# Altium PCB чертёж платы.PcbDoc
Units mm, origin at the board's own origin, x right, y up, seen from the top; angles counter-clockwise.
Board outline 152.4 x 101.6 mm, 2 copper layers (Top Layer, Bottom Layer); 38 components, 63 nets, 180 pads, 31 vias.
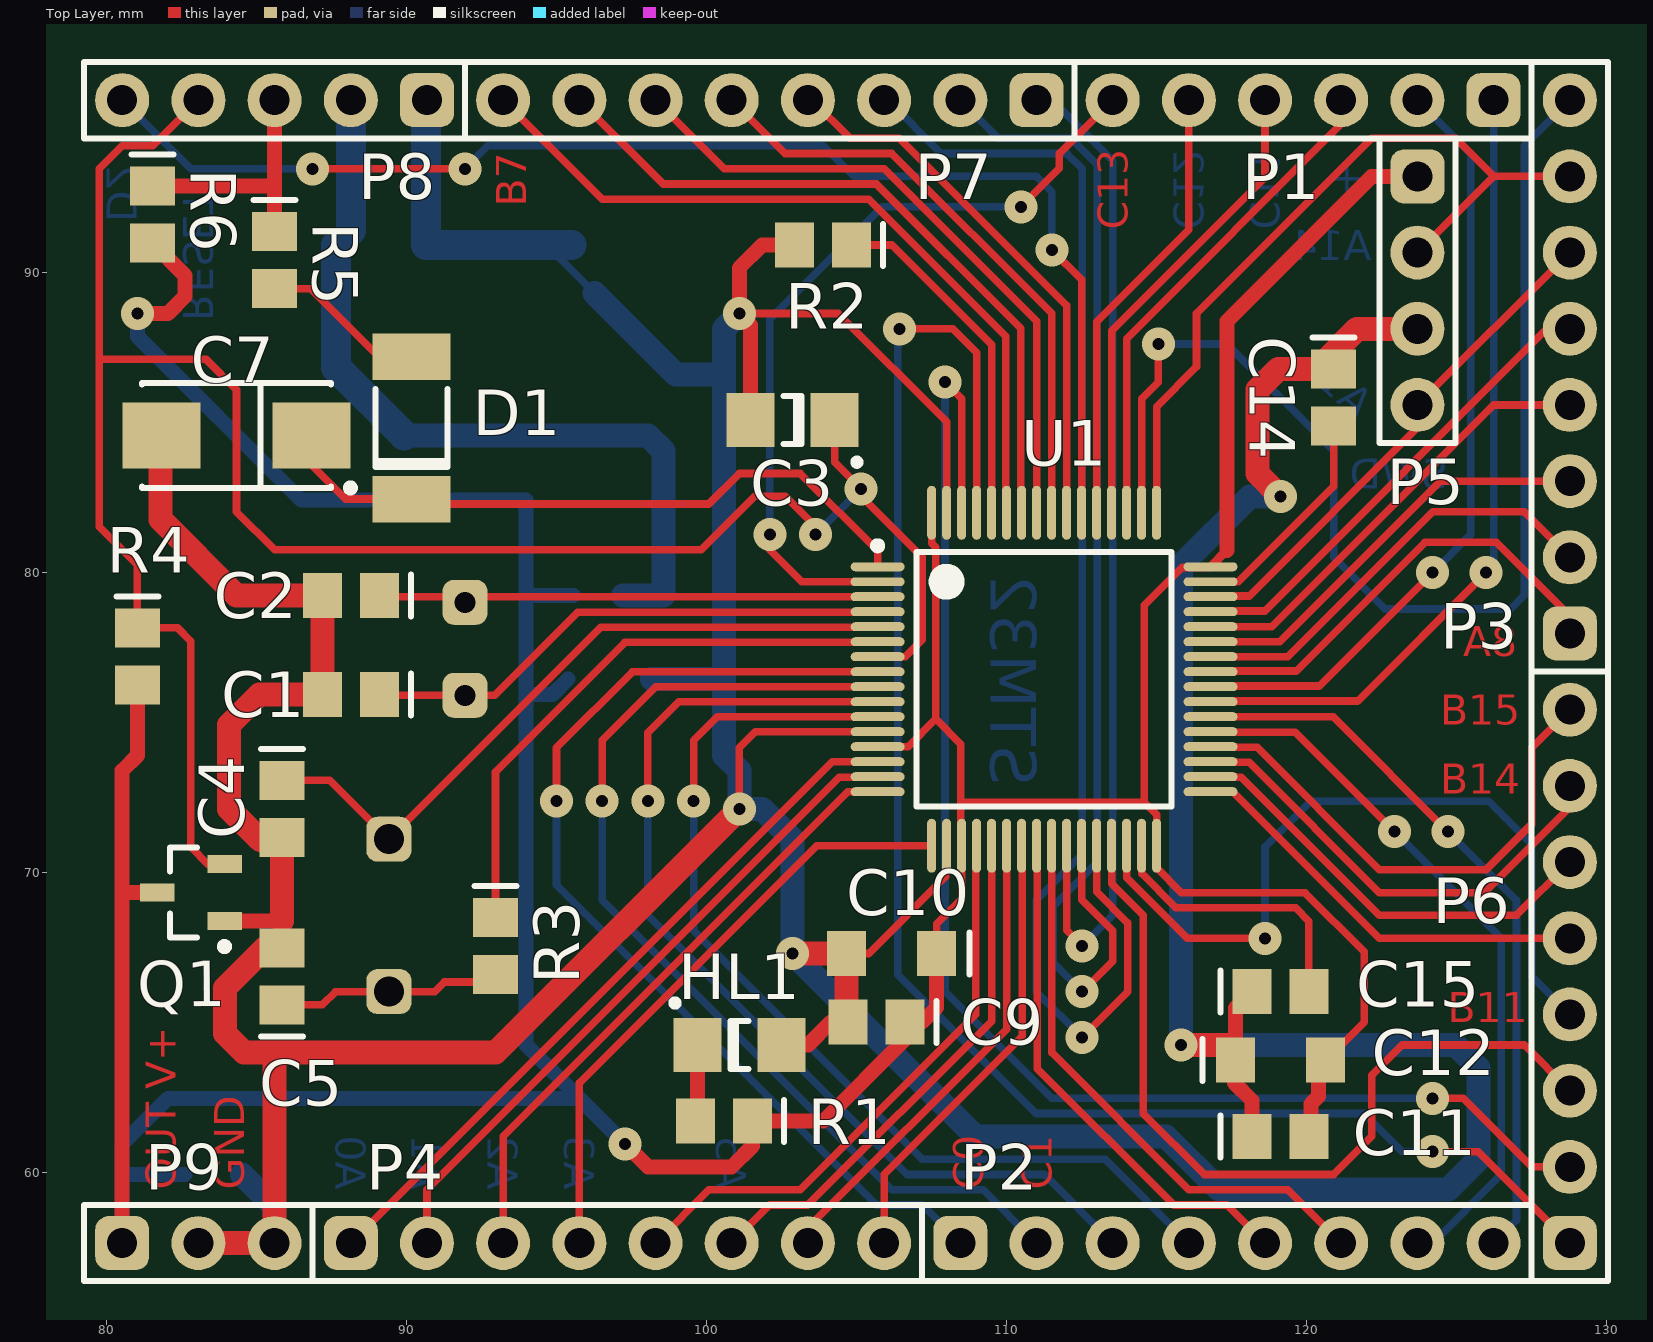
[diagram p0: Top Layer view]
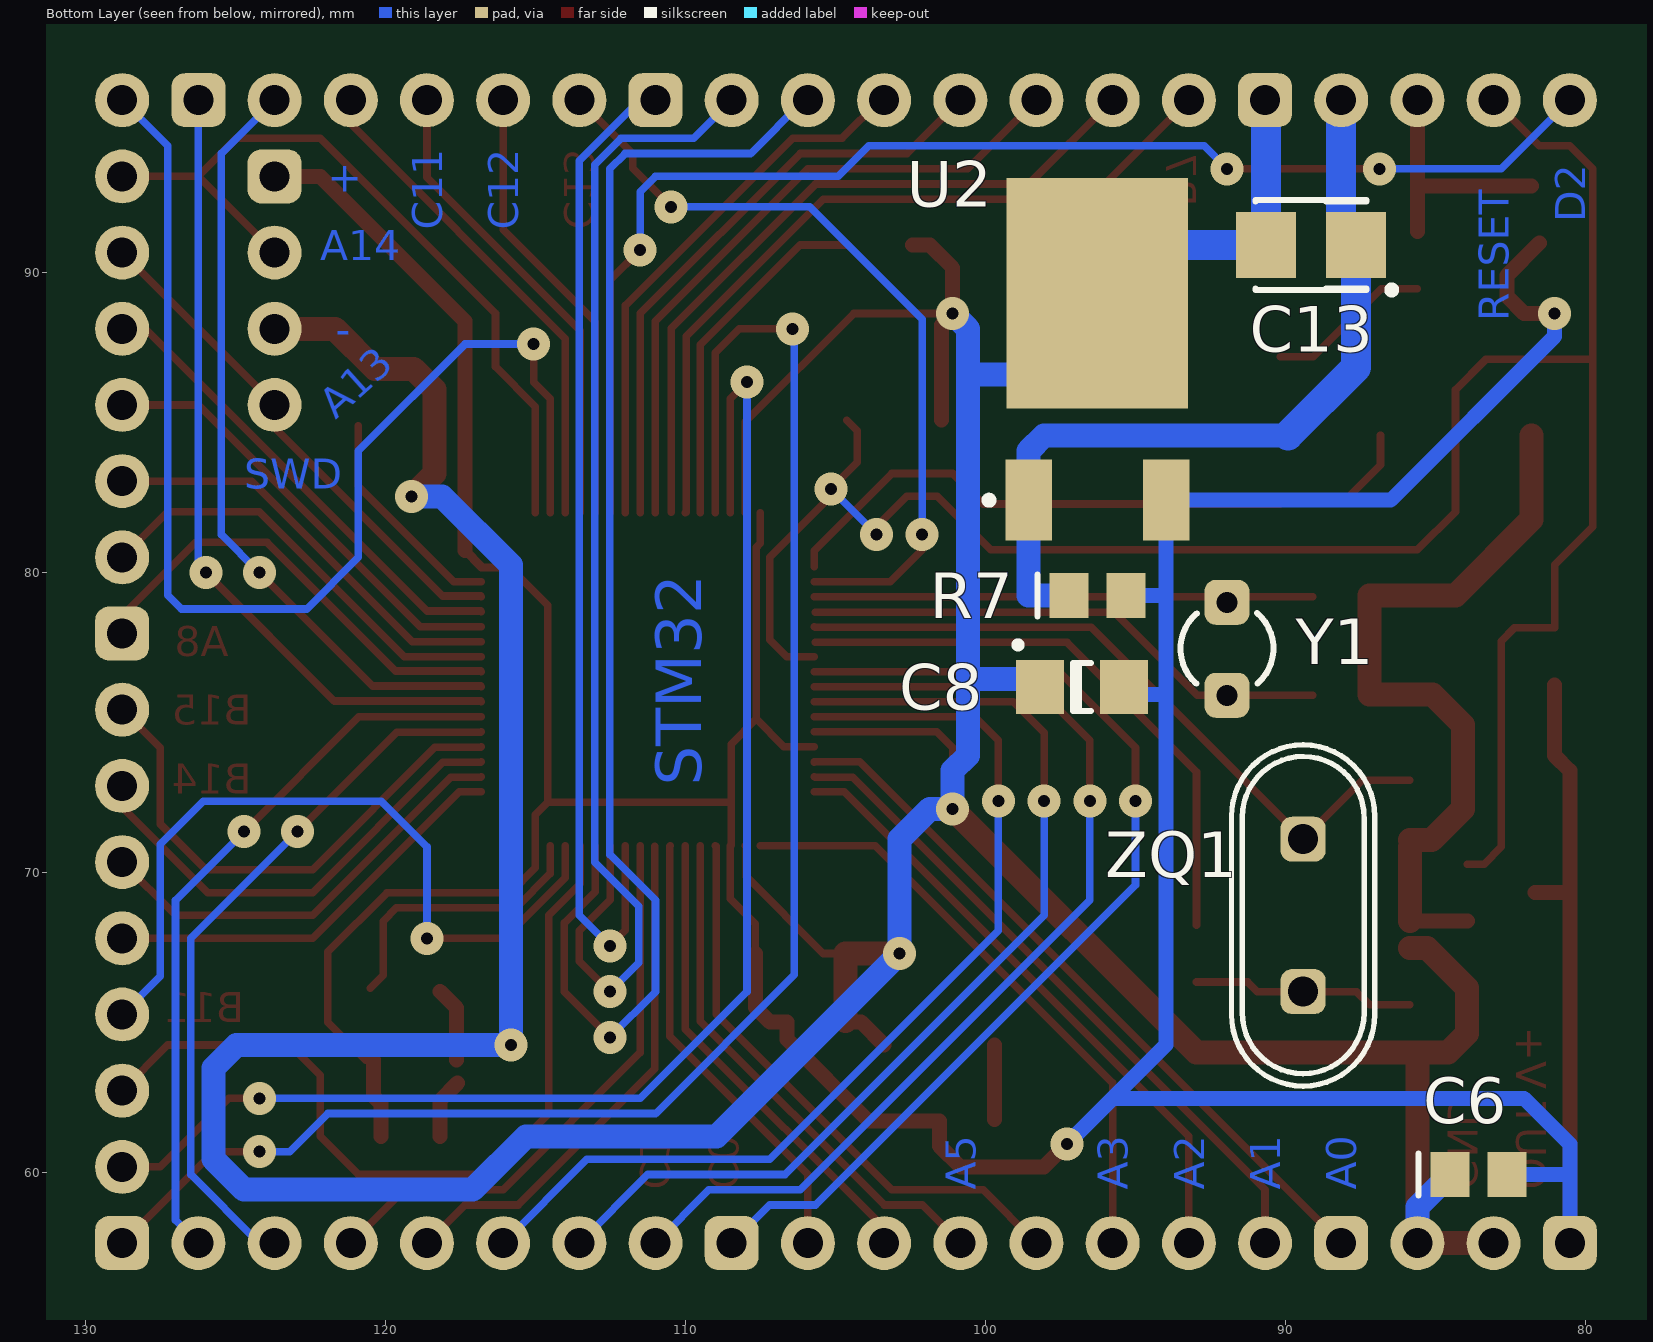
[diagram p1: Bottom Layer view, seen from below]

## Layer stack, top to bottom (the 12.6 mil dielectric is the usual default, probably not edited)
Top Solder: solder mask 0.0102, Solder Resist, Dk 3.5
Top Layer: signal copper 0.0356
Dielectric1: dielectric 0.32, FR-4, Dk 4.8
Bottom Layer: signal copper 0.0356
Bottom Solder: solder mask 0.0102, Solder Resist, Dk 3.5

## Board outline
25.4,25.4 177.8,25.4 177.8,127 25.4,127

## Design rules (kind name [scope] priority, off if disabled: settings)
Clearance [All] p1: gap=0.2
PlaneConnect [All] p1: planeconnectstyle=Relief reliefexpansion=0.254 reliefentries=4 reliefconductorwidth=0.254 reliefairgap=0.254
PolygonConnect [All] p1: connectstyle=Relief reliefconductorwidth=0.254 reliefentries=4 polygonreliefangle="45 Angle" airgapwidth=0.254
RoomDefinition Sheet1 [InComponentClass('Sheet1')] p1: confinementstyle=ConfineIn formatcopy=TRUE lockcomponents=FALSE outline 79.056,56.388 130.048,56.388 130.048,97.028 79.056,97.028
RoutingCorners [All] p1: cornerstyle=Round minsetback=2.54 maxsetback=2.54
RoutingVias [All] p1: holewidth=0.5 width=1.3 viastyle="Through Hole" minholewidth=0.5 minwidth=1 maxholewidth=0.5 maxwidth=1.5
SolderMaskExpansion [All] p1: expansion=0.2
UnpouredPolygon [All] p1: allowunpoured=FALSE
Width [All] p1: maxlimit=2 minlimit=0.254 preferedwidth=0.3
27 further rules are at their usual default settings.

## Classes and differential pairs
component class Sheet1: C1 C2 C3 C4 C5 C6 C7 C8 C9 C10 C11 C12 C13 C14 C15 D1 HL1 P1 P2 P5 P6 P7 P8 P9 Q1 R1 R3 R4 R5 R6 R7 U1 U2 Y1 ZQ1

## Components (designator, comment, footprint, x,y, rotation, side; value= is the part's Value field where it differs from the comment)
C1 "Cap Semi" C0805 88.138,75.946 r180 top
C2 "Cap Semi" C0805 88.138,79.248 r180 top
C3 "Cap Semi" C1206 102.87,85.09 r180 top
C4 "Cap Semi" C0805 85.852,72.136 r270 top
C5 "Cap Semi" C0805 85.852,66.548 r90 top
C6 "Cap Semi" C0805 83.566,59.944 r180 bottom
C7 "Cap Semi" "6032 - Type C" 84.328,84.582 r180 top
C8 "Cap Semi" C1206 96.774,76.2 r180 bottom
C9 "Cap Semi" C0805 105.664,65.024 r180 top
C10 "Cap Semi" "C0805 - wa" 106.172,67.31 r180 top
C11 "Cap Semi" C0805 119.126,61.214 r0 top
C12 "Cap Semi" "C0805 - wa" 119.126,63.754 r0 top
C13 "Cap polar_Vishay Type B" "3528 - Type B" 89.154,90.932 r0 bottom
C14 "Cap Semi" C0805 120.904,85.852 r270 top
C15 "Cap Semi" C0805 119.126,66.04 r0 top
D1 "1n4148" MELF 90.17,84.836 r270 top
HL1 "FYLS-3528UYC" C1206 101.092,64.262 r0 top
P1 "port C 8-13" HDR1X6 126.238,95.758 r180 top
P2 "port C 0-7" HDR1X8 108.458,57.658 r0 top
P3 "port A 8-15" HDR1X8 128.778,77.978 r90 top
P4 "port A 0-7" HDR1X8 88.138,57.658 r0 top
P5 "programmer" HDR1X4 123.698,93.218 r270 top
P6 "port B 8-15" HDR1X8 128.778,57.658 r90 top
P7 "port B 0-7" HDR1X8 110.998,95.758 r180 top
P8 "Header 5" HDR1X5 90.678,95.758 r180 top
P9 "Header 3" HDR1X3 80.518,57.658 r0 top
Q1 "STM809" SOT-23B_N 82.804,69.342 r180 top
R1 "Res2" C0805 100.584,61.722 r180 top
R2 "Res2" C0805 103.886,90.932 r180 top
R3 "Res2" C0805 92.964,67.564 r270 top
R4 "Resistor 1206" C0805 81.026,77.216 r270 top
R5 "Res2" C0805 85.598,90.424 r270 top
R6 "Res2" C0805 81.534,91.948 r270 top
R7 "Res2" C0805 96.266,79.248 r180 bottom
U1 "STM32F107RCT6TR" LQFP64_N 111.252,76.454 r0 top
U2 "ARU1206K-33" DPAK 96.266,87.122 r90 bottom
Y1 "32768 Hz" R38 91.948,77.47 r0 bottom
ZQ1 "8 MHz" HC49S 89.408,68.58 r90 bottom

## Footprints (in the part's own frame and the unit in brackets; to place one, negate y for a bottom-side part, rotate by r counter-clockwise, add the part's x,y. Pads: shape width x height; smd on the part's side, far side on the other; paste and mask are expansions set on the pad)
"3528 - Type B" [mm] "Capacitor, SM Tantalum; Body 3.5 x 2.8 mm (LxW typ)"
  rect 2x2.2 smd: 1(-1.5,0) 2(1.5,0)
  silkscreen extent -2.82,-1.5 1.85,1.62
"6032 - Type C" [mm] "Capacitor, SM Tantalum; Body 6.0 x 3.2 mm (LxW typ)"
  rect 2.6x2.2 smd: 1(-2.5,0) 2(2.5,0)
  silkscreen extent -3.93,-1.75 3.15,1.87
C0805 [mm] "Chip Capacitor; Body 2.0 x 1.2 mm (LxW typ)"
  rect 1.3x1.5 smd: 1(-0.95,0) 2(0.95,0)
  silkscreen extent -2,-0.7 -2,0.7
"C0805 - wa" [mm] "Chip Capacitor; Body 2.0 x 1.2 mm (LxW typ)"
  rect 1.3x1.5 smd: 1(-1.5,0) 2(1.5,0)
  silkscreen extent -2.6,-0.7 -2.6,0.7
C1206 [mm] "Chip Capacitor; Body 3.2 x 1.6 mm (LxW typ)"
  rect 1.6x1.8 smd: 1(-1.4,0) 2(1.4,0)
  silkscreen extent -2.18,-0.8 0.3,1.44
DPAK [mm] "D-PAK, 3-Pads, Body 6,2x6,6mm (max), IPC Medium Density"
  rect 2.7x1.55 smd: 1(-4.7,2.29) 3(-4.7,-2.29)
  rect 7.7x6.05 smd: 2(2.2,0)
  silkscreen extent -4.82,3.49 -4.58,3.74, body extent -5.59,-3.3 4.51,3.3, height 2.4
HC49S [mm]
  rrect50% 1.5x1.5 hole 1: 1(-2.54,0) 2(2.54,0)
  silkscreen extent -5.69,-2.39 5.69,2.39
HDR1X3 [mm] "Connector; Header; 3 Position"
  rrect50% 1.8x1.8 hole 1: 1(0,0)
  round 1.8 hole 1: 2(2.54,0) 3(5.08,0)
  silkscreen extent -1.27,-1.27 6.35,1.27
HDR1X4 [mm] "Connector; Header; 4 Position"
  rrect50% 1.8x1.8 hole 1: 1(0,0)
  round 1.8 hole 1: 2(2.54,0) 3(5.08,0) 4(7.62,0)
  silkscreen extent -1.27,-1.27 8.89,1.27
HDR1X5 [mm] "Connector; Header; 5 Position"
  rrect50% 1.8x1.8 hole 1: 1(0,0)
  round 1.8 hole 1: 2(2.54,0) 3(5.08,0) 4(7.62,0) 5(10.16,0)
  silkscreen extent -1.27,-1.27 11.43,1.27
HDR1X6 [mm] "Connector; Header; 6 Position"
  rrect50% 1.8x1.8 hole 1: 1(0,0)
  round 1.8 hole 1: 2(2.54,0) 3(5.08,0) 4(7.62,0) 5(10.16,0) 6(12.7,0)
  silkscreen extent -1.27,-1.27 13.97,1.27
HDR1X8 [mm] "Connector; Header; 8 Position"
  rrect50% 1.8x1.8 hole 1: 1(0,0)
  round 1.8 hole 1: 2(2.54,0) 3(5.08,0) 4(7.62,0) 5(10.16,0) 6(12.7,0) 7(15.24,0) 8(17.78,0)
  silkscreen extent -1.27,-1.27 19.05,1.27
LQFP64_N [mm] "Thin QFP, 64-Leads, Body 10x10mm, Pitch 0.5mm, IPC Medium Density"
  oval 1.8x0.3 smd: 1(-5.55,3.75) 2(-5.55,3.25) 3(-5.55,2.75) 4(-5.55,2.25) 5(-5.55,1.75) 6(-5.55,1.25) 7(-5.55,0.75) 8(-5.55,0.25) 9(-5.55,-0.25) 10(-5.55,-0.75) 11(-5.55,-1.25) 12(-5.55,-1.75) 13(-5.55,-2.25) 14(-5.55,-2.75) 15(-5.55,-3.25) 16(-5.55,-3.75) 33(5.55,-3.75) 34(5.55,-3.25) 35(5.55,-2.75) 36(5.55,-2.25) 37(5.55,-1.75) 38(5.55,-1.25) 39(5.55,-0.75) 40(5.55,-0.25) 41(5.55,0.25) 42(5.55,0.75) 43(5.55,1.25) 44(5.55,1.75) 45(5.55,2.25) 46(5.55,2.75) 47(5.55,3.25) 48(5.55,3.75)
  oval 0.3x1.8 smd: 17(-3.75,-5.55) 18(-3.25,-5.55) 19(-2.75,-5.55) 20(-2.25,-5.55) 21(-1.75,-5.55) 22(-1.25,-5.55) 23(-0.75,-5.55) 24(-0.25,-5.55) 25(0.25,-5.55) 26(0.75,-5.55) 27(1.25,-5.55) 28(1.75,-5.55) 29(2.25,-5.55) 30(2.75,-5.55) 31(3.25,-5.55) 32(3.75,-5.55) 49(3.75,5.55) 50(3.25,5.55) 51(2.75,5.55) 52(2.25,5.55) 53(1.75,5.55) 54(1.25,5.55) 55(0.75,5.55) 56(0.25,5.55) 57(-0.25,5.55) 58(-0.75,5.55) 59(-1.25,5.55) 60(-1.75,5.55) 61(-2.25,5.55) 62(-2.75,5.55) 63(-3.25,5.55) 64(-3.75,5.55)
  silkscreen extent -5.67,-4.25 4.25,4.57, body extent -5,-5 5,5, height 1.6
MELF [mm] "Metal Electrode Face (MELF) Diode; Body 5 x 2.5 mm (LxDia)"
  rect 1.55x2.6 smd: 1(-2.375,0) 2(2.375,0)
  silkscreen extent -1.3,-1.2 1.3,1.2
R38 [mm] "Crystal, Thru-Hole; 2 Leads; Body 3.1 x 8.2 mm (Dia.xH)"
  rrect50% 1.5x1.5 hole 0.7: 1(0,1.55) 2(0,-1.55)
  silkscreen extent -1.55,-1.19 1.55,1.17
SOT-23B_N [mm] "SOT23, 3-Leads, Body 2.9x1.3mm, Pitch 0.95mm, Lead Span 2.4mm, IPC Medium Density"
  rect 1.15x0.6 smd: 1(-1.125,0.95) 2(-1.125,-0.95) 3(1.125,0)
  silkscreen extent -1.25,-1.5 0.7,1.92, body extent -0.7,-1.5 0.7,1.5, height 1.14

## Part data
C1 C2 C3 C4 C5 C6 C7 C8 C9 C10 C11 C12 C14 C15: "Capacitor (Semiconductor SIM Model)"
C13: "Capacitor (Model Sergeev)"
D1: library part SM4001, "Диод SMD 1A, 1000V"
HL1: library part "LED CMD", "Typical INFRARED GaAs LED"
P1: library part "Header 6", "Header, 6-Pin"
P2 P3 P4 P6 P7: library part "Header 8", "Header, 8-Pin"
P5: library part "Header 4", "Header, 4-Pin"
P8: "Header, 5-Pin"
P9: "Header, 3-Pin"
Q1: library part PNP, "PNP Bipolar Transistor"
R1 R2 R3 R5 R6 R7: "Resistor"
U1: "STM32 ARM-based 32-bit MCU Connectivity Line & Ethernet with 256 kB Flash, 64 kB Internal RAM, -40 to +85°C Temperature, 64-Pin LQFP, Tape and Reel"
U2: library part L7805ABV, "Precision 1A Regulator"
Y1 ZQ1: library part XTAL, "Crystal Oscillator"

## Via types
v1: diameter 1.1, hole 0.4, Top Layer to Bottom Layer, tented both sides, 31 vias

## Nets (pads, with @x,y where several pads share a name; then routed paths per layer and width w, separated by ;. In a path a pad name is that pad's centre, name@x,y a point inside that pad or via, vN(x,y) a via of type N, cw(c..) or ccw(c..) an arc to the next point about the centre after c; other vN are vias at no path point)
GND: C1.2 C2.2 C3.2 C4.2 C5.2 C6.1 C7.2 C8.1 C9.2 C10.2 C11.1 C12.1 C13.2 C14.1 C15.1 HL1.2 P5.3 P8.1 P9.2 P9.3 Q1.1 R2.2 U1.12 U1.18 U1.63 U2.2 | length 217.1
  Top Layer w0.254: v1(101.092,72.136) 101.092,74.168 101.628,74.704 U1.12 ; v1(101.092,88.646) 104.394,88.646 108.002,85.038 U1.63 ; C10.2 105.41,67.31 107.979,69.879 107.979,70.881 U1.18
  Top Layer w0.5: Q1.1 85.852,68.392 ; C3.2 101.47,88.268 v1(101.092,88.646) 101.092,90.17 101.854,90.932 R2.2@102.428,90.932 ; 103.378,64.262 104.14,65.024 C9.2 ; 117.602,62.992 118.176,62.418 C11.1 ; C12.1 117.626,65.49 C15.1
  Top Layer w0.8: C7.2@81.803,84.582 81.803,81.773 84.328,79.248 C2.2 C1.2 85.09,75.946 84.074,74.93 84.074,72.136 85.121,71.089 C4.2@85.852,71.089 ; P9.2 P9.3 85.598,64.008 ; C5.2 85.278,67.498 83.947,66.167 83.947,64.643 84.582,64.008 85.598,64.008 ; 85.852,68.392 C4.2@85.852,70.866 ; v1(101.092,72.136) 92.964,64.008 85.598,64.008 ; v1(102.87,67.31) C10.2 C9.2@104.672,65.066 ; v1(115.824,64.262) C12.1@117.372,64.262 ; v1(119.126,82.55) 118.364,83.312 118.364,86.106 119.06,86.802 120.354,86.802 121.69,88.138 P5.3
  Bottom Layer w0.254: P8.1@90.654,95.782 P8.1 ; U2.2@94.656,90.932 U2.2
  Bottom Layer w0.8: C6.1 85.598,58.862 P9.3 ; U2.2 98.974,86.614 100.584,86.614 ; C8.1@98.174,76.454 100.584,76.454 ; v1(101.092,88.646) 100.584,88.138 100.584,86.614 ; v1(119.126,82.55) 118.11,82.55 115.824,80.264 v1(115.824,64.262) 124.968,64.262 125.73,63.5 125.73,60.452 124.714,59.436 117.094,59.436 115.316,61.214 108.966,61.214 v1(102.87,67.31) 102.87,71.12 101.854,72.136 v1(101.092,72.136) 101.092,73.406 100.584,73.914 100.584,76.454 ; 100.584,76.454 100.584,86.614
  Bottom Layer w1: P8.1@90.654,95.782 C13.2 U2.2@95.504,90.932
NetC1_1: C1.1 U1.4 Y1.1 | length 17.7
  Top Layer w0.254: C1.1@89.088,75.92 92.938,75.92 95.699,78.681 U1.4@105.679,78.681
NetC2_1: C2.1 U1.3 Y1.2 | length 16.6
  Top Layer w0.254: C2.1@89.088,79.204 U1.3
NetC3_1: C3.1 P8.4 Q1.2 R4.1 U1.7 | length 73.1
  Top Layer w0.254: 79.756,86.868 79.756,89.662 79.756,93.472 80.518,94.234 81.534,94.234 P8.4 ; Q1.2 83.378,70.292 82.804,70.866 82.804,77.724 82.362,78.166 R4.1 81.026,80.264 79.756,81.534 79.756,87.122 83.312,87.122 84.328,86.106 84.328,82.042 85.598,80.772 99.822,80.772 101.6,82.55 102.616,82.55 103.632,81.534 v1(103.632,81.28) ; C3.1@104.624,85.09 104.27,84.736 104.27,83.69 v1(105.156,82.804) ; v1@105.156,82.55 107.188,80.518 107.188,77.765 106.627,77.204 U1.7
  Bottom Layer w0.254: v1(103.632,81.28) v1(105.156,82.804)
NetC4_1: C4.1 U1.5 ZQ1.2 | length 23.6
  Top Layer w0.254: C4.1 87.442,73.086 ZQ1.2 96.469,78.181 105.679,78.181 U1.5
NetC5_1: C5.1 R3.2 ZQ1.1 | length 7.4
  Top Layer w0.254: C5.1 87.188,65.598 87.63,66.04 ZQ1.1 90.932,66.04 91.252,66.36 R3.2@92.964,66.36
NetC6_2: C6.2 C8.2 C9.1 C10.1 C11.2 C12.2 P5.1 P9.1 Q1.3 R1.1 R4.2 R6.2 R7.2 U1.13 U1.19 U1.32 U1.48 U1.64 U2.3 | length 172.1
  Top Layer w0.254: U1.13 106.716,74.204 107.642,75.13 ; U1.64 107.502,80.986 107.642,80.846 107.642,75.13 ; C10.1 107.672,68.302 108.502,69.132 U1.19 ; U1.19@108.479,70.927 108.479,72.352 ; U1.48 116.779,80.181 115.854,80.181 114.592,78.919 114.592,72.352 ; C12.2@120.65,63.754 121.92,65.024 121.92,67.37 119.948,69.342 115.824,69.342 115.002,70.164 U1.32 115.002,71.942 114.592,72.352 ; 107.642,75.13 108.479,74.293 108.479,72.352 ; 108.479,72.352 114.592,72.352
  Top Layer w0.3: U1.48 117.348,80.75
  Top Layer w0.5: P9.1 80.518,69.342 ; R4.2 81.026,73.914 80.518,73.406 80.518,69.342 ; v1(81.026,88.646) 82.042,88.646 82.616,89.22 82.616,89.916 R6.2 ; Q1.3 80.518,69.342 ; v1(97.282,60.96) 98.044,60.198 100.838,60.198 101.534,60.894 R1.1 103.886,61.722 106.614,64.45 C9.1 107.188,65.024 107.672,65.508 C10.1 ; 117.348,80.75 117.348,88.392 122.174,93.218 P5.1 ; C11.2@120.142,61.214 120.142,62.296 120.396,62.55 C12.2@120.396,63.754
  Bottom Layer w0.5: P9.1 80.518,60.96 82.042,62.484 95.758,62.484 v1(97.282,60.96) 93.976,64.266 93.976,79.252 ; 80.518,59.944 C6.2 ; v1(81.026,88.646) 81.026,87.884 86.488,82.422 U2.3 93.976,79.252 ; 93.976,75.946 94.866,75.946 C8.2@95.374,76.454 ; R7.2@95.57,79.248 93.98,79.248 93.976,79.252
NetC7_1: C7.1 D1.2 U1.1 | length 22.3
  Top Layer w0.254: C7.1 86.828,83.606 87.973,82.461 D1.2 ; D1.2@90.17,82.296 100.076,82.296 101.092,83.312 103.124,83.312 105.702,80.734 U1.1
NetC13_1: C13.1 P8.2 R7.1 U2.1 | length 27.3
  Bottom Layer w0.5: C13.1 C13.1@88.138,91.416
  Bottom Layer w0.8: 89.916,84.582 98.044,84.582 98.556,84.07 U2.1 98.556,79.252 98.552,79.248 R7.1
  Bottom Layer w1: C13.1 87.654,86.844 89.916,84.582 ; C13.1@88.138,91.416 P8.2
NetC14_2: C14.2 U1.47 | length 7.4
  Top Layer w0.254: U1.47 117.727,79.704 120.904,82.881 C14.2
NetC15_2: C15.2 U1.31 | length 9.6
  Top Layer w0.254: U1.31 114.502,69.979 115.647,68.834 119.634,68.834 120.076,68.392 120.076,66.59 C15.2@120.511,66.155
NetD1_1: D1.1 R5.2 | length 5.5
  Top Layer w0.254: R5.2 86.802,89.474 89.065,87.211 D1.1
NetHL1_1: HL1.1 R1.2 | length 2.5
  Top Layer w0.5: R1.2@99.692,61.78 HL1.1
NetP1_1: P1.1 U1.39 | length 26.9
  Top Layer w0.254: U1.39 116.825,75.727 121.701,75.727 v1(125.984,80.01)
  Bottom Layer w0.254: v1(125.984,80.01) 126.238,80.264 126.238,95.504 P1.1@125.984,95.758
NetP1_2: P1.2 U1.40 | length 26
  Top Layer w0.254: U1.40 116.825,76.227 120.423,76.227 v1(124.206,80.01)
  Bottom Layer w0.254: P1.2 125.476,93.98 125.476,81.28 v1(124.206,80.01)
NetP1_3: P1.3 U1.51 | length 16.7
  Top Layer w0.254: U1.51 114.002,87.81 121.158,94.966 P1.3
NetP1_4: P1.4 U1.52 | length 15.9
  Top Layer w0.254: U1.52 113.502,88.073 118.618,93.189 P1.4
NetP1_5: P1.5 U1.53 | length 15
  Top Layer w0.254: U1.53 113.002,88.364 116.078,91.44 P1.5
NetP1_6: P1.6 U1.2 | length 26.5
  Top Layer w0.254: v1(102.108,81.28) 102.108,80.772 103.176,79.704 U1.2 ; v1(110.474,92.202) 111.76,93.488 111.76,93.98 P1.6
  Bottom Layer w0.254: v1(102.108,81.28) 102.108,88.458 105.852,92.202 v1(110.474,92.202)
NetP2_1: P2.1 U1.8 | length 35
  Top Layer w0.254: v1@94.996,72.136 94.996,74.168 97.532,76.704 U1.8
  Bottom Layer w0.254: v1(94.996,72.39) 94.996,69.596 105.664,58.928 107.188,58.928 P2.1
NetP2_2: P2.2 U1.9 | length 34.7
  Top Layer w0.254: v1@96.52,72.136 96.52,74.422 98.302,76.204 U1.9
  Bottom Layer w0.254: v1(96.52,72.39) 96.52,69.088 106.172,59.436 109.22,59.436 P2.2
NetP2_3: P2.3 U1.10 | length 34.5
  Top Layer w0.254: v1@98.044,72.136 98.044,74.676 99.072,75.704 U1.10
  Bottom Layer w0.254: v1(98.044,72.39) 98.044,68.58 106.68,59.944 111.252,59.944 P2.3
NetP2_4: P2.4 U1.11 | length 33.6
  Top Layer w0.254: v1(99.568,72.39) 99.568,74.422 100.35,75.204 U1.11
  Bottom Layer w0.254: v1(99.568,72.39) 99.568,68.072 107.188,60.452 113.284,60.452 P2.4
NetP2_5: P2.5 U1.24 | length 17.4
  Top Layer w0.254: U1.24@111.025,70.881 111.025,63.473 115.57,58.928 117.348,58.928 P2.5
NetP2_6: P2.6 U1.25 | length 19.2
  Top Layer w0.254: U1.25 111.502,64.012 116.078,59.436 119.38,59.436 P2.6
NetP2_7: P2.7 U1.37 | length 24.2
  Top Layer w0.254: U1.37 116.825,74.681 119.629,74.681 v1(122.936,71.374)
  Bottom Layer w0.254: v1(122.936,71.374) 126.492,67.818 126.492,59.944 124.206,57.658 P2.7
NetP2_8: P2.8 U1.38 | length 24.5
  Top Layer w0.254: U1.38 120.884,75.204 v1(124.714,71.374)
  Bottom Layer w0.254: v1(124.714,71.374) 127,69.088 127,58.42 P2.8
NetP3_1: P3.1 U1.41 | length 15.4
  Top Layer w0.254: U1.41 116.825,76.727 119.653,76.727 123.952,81.026 126.328,81.026 128.778,78.576 P3.1
NetP3_2: P3.2 U1.42 | length 14.6
  Top Layer w0.254: U1.42 119.368,77.204 124.206,82.042 127.254,82.042 P3.2
NetP3_3: P3.3 U1.43 | length 14.2
  Top Layer w0.254: U1.43 119.106,77.704 124.46,83.058 P3.3
NetP3_4: P3.4 U1.44 | length 15
  Top Layer w0.254: U1.44 118.844,78.204 126.238,85.598 P3.4
NetP3_5: P3.5 U1.45 | length 15.9
  Top Layer w0.254: U1.45 116.825,78.727 118.605,78.727 128.016,88.138 P3.5
NetP3_6: P3.6 P5.4 U1.46 | length 17.2
  Top Layer w0.254: U1.46 116.825,79.227 118.089,79.227 123.698,84.836 P5.4 P3.6
NetP3_7: P3.7 P5.2 U1.49 | length 26.2
  Top Layer w0.254: U1.49 115.002,85.538 116.332,86.868 116.332,88.646 122.174,94.488 124.968,94.488 126.238,93.218 ; P5.2 126.238,93.218 ; P3.7 126.238,93.218
NetP3_8: P3.8 U1.50 | length 41.1
  Top Layer w0.254: U1.50 114.502,85.8 115.062,86.36 v1(115.062,87.63)
  Bottom Layer w0.254: v1(115.062,87.63) 117.348,87.63 120.904,84.074 120.904,80.518 122.628,78.794 126.8,78.794 127.254,79.248 127.254,94.234 P3.8
NetP4_1: P4.1 U1.14 | length 24.2
  Top Layer w0.254: P4.1 104.184,73.704 U1.14 U1.14@105.702,73.681
NetP4_2: P4.2 U1.15 | length 22.5
  Top Layer w0.254: P4.2 90.678,59.436 104.423,73.181 105.679,73.181 U1.15
NetP4_3: P4.3 U1.16 | length 20.8
  Top Layer w0.254: P4.3 93.218,61.214 104.708,72.704 U1.16
NetP4_4: P4.4 U1.17 | length 20.4
  Top Layer w0.254: P4.4 95.758,62.992 103.67,70.904 U1.17
NetP4_5: P4.5 U1.20 | length 19.5
  Top Layer w0.254: P4.5 100.076,59.436 103.124,59.436 108.979,65.291 108.979,70.881 U1.20
NetP4_6: P4.6 U1.21 | length 17.6
  Top Layer w0.254: P4.6 102.108,58.928 103.378,58.928 109.502,65.052 U1.21
NetP4_7: P4.7 U1.22 | length 16
  Top Layer w0.254: P4.7 103.378,58.166 110.002,64.79 U1.22
NetP4_8: P4.8 U1.23 | length 15.2
  Top Layer w0.254: P4.8 105.918,59.944 110.525,64.551 110.525,70.881 U1.23
NetP6_1: P6.1 U1.61 | length 55.9
  Top Layer w0.254: v1(106.426,88.138) 108.204,88.138 109.002,87.34 U1.61 ; v1(124.206,60.706) 125.73,60.706 P6.1
  Bottom Layer w0.254: v1@106.372,88.138 106.372,66.602 110.998,61.976 121.92,61.976 123.19,60.706 v1(124.206,60.706)
NetP6_2: P6.2 U1.62 | length 48.2
  Top Layer w0.254: v1(107.95,86.36) 108.502,85.808 U1.62 ; v1(124.206,62.484) 125.222,62.484 127.508,60.198 P6.2
  Bottom Layer w0.254: v1(107.95,86.36) 107.95,66.04 111.506,62.484 v1(124.206,62.484)
NetP6_3: P6.3 U1.29 | length 28
  Top Layer w0.254: U1.29 113.502,69.632 114.554,68.58 114.554,61.976 116.586,59.944 120.904,59.944 122.174,61.214 122.174,63.246 123.19,64.262 127.254,64.262 P6.3
NetP6_4: P6.4 U1.30 | length 25.9
  Top Layer w0.254: U1.30 114.002,69.837 116.021,67.818 v1(118.618,67.818)
  Bottom Layer w0.254: v1(118.618,67.818) 118.618,70.866 120.142,72.39 126.074,72.39 127.508,70.956 127.508,66.548 P6.4
NetP6_5: P6.5 U1.33 | length 14
  Top Layer w0.254: U1.33 117.542,72.704 122.428,67.818 P6.5
NetP6_6: P6.6 U1.34 | length 14.6
  Top Layer w0.254: U1.34 116.825,73.181 117.827,73.181 122.428,68.58 127,68.58 P6.6
NetP6_7: P6.7 U1.35 | length 15.7
  Top Layer w0.254: U1.35 116.825,73.681 118.089,73.681 122.428,69.342 125.93,69.342 128.778,72.19 P6.7
NetP6_8: P6.8 U1.36 | length 17.4
  Top Layer w0.254: U1.36 116.825,74.181 118.351,74.181 122.428,70.104 125.984,70.104 127.508,71.628 127.508,74.168 P6.8
NetP7_1: P7.1 U1.26 | length 33.5
  Top Layer w0.254: U1.26 112.002,68.084 v1(112.522,67.564)
  Bottom Layer w0.254: P7.1 111.52,95.758 113.538,93.74 113.538,68.58 v1(112.522,67.564)
NetP7_2: P7.2 U1.27 | length 39.8
  Top Layer w0.254: U1.27 112.502,69.108 113.538,68.072 113.538,67.056 v1(112.522,66.04)
  Bottom Layer w0.254: P7.2 109.728,94.488 112.148,94.488 113.03,93.606 113.03,70.358 111.56,68.888 111.56,67.002 v1(112.522,66.04)
NetP7_3: P7.3 U1.28 | length 45.2
  Top Layer w0.254: v1(112.522,64.516) 114.046,66.04 114.046,68.326 113.002,69.37 U1.28
  Bottom Layer w0.254: P7.3 106.052,95.758 107.83,93.98 112.014,93.98 112.522,93.472 112.522,70.612 110.998,69.088 110.998,66.04 v1(112.522,64.516)
NetP7_4: P7.4 U1.55 | length 18.4
  Top Layer w0.254: P7.4 103.512,95.758 104.782,94.488 106.426,94.488 112.002,88.912 U1.55
NetP7_5: P7.5 U1.56 | length 20.3
  Top Layer w0.254: P7.5 102.616,93.98 106.172,93.98 111.502,88.65 U1.56
NetP7_6: P7.6 U1.57 | length 22.1
  Top Layer w0.254: P7.6 100.584,93.472 105.918,93.472 111.002,88.388 U1.57
NetP7_7: P7.7 U1.58 | length 24
  Top Layer w0.254: P7.7 98.552,92.964 105.664,92.964 110.479,88.149 U1.58@110.479,82.027
NetP7_8: P7.8 U1.59 | length 25.9
  Top Layer w0.254: P7.8 96.52,92.456 105.41,92.456 109.979,87.887 109.979,82.027 U1.59
NetP8_3: P8.3 R5.1 R6.1 | length 8.2
  Top Layer w0.5: R6.1@81.788,92.898 85.598,92.898 ; R5.1 85.598,92.898 ; P8.3 85.598,92.898
NetP8_5: P8.5 U1.54 | length 44
  Top Layer w0.254: v1(86.868,93.472) v1(91.948,93.472) ; v1(111.511,90.764) 112.502,89.772 U1.54
  Bottom Layer w0.254: P8.5 82.804,93.472 v1(86.868,93.472) ; v1(91.948,93.472) 92.71,94.234 103.886,94.234 104.902,93.218 110.998,93.218 111.506,92.71 111.506,90.768 v1(111.511,90.764)
NetR2_1: R2.1 U1.60 | length 11.9
  Top Layer w0.254: R2.1@104.582,90.932 106.172,90.932 109.502,87.602 U1.60
NetR3_1: R3.1 U1.6 | length 19.6
  Top Layer w0.254: R3.1@92.964,68.26 92.964,73.363 97.282,77.681 U1.6@105.679,77.681

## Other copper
Top Layer:
  text "B7" at 93.98,92.202 h1 r90
  text "C13" at 114.046,91.44 h1 r90
  text "A8" at 125.222,77.216 h1
  text "B15" at 124.46,74.93 h1
  text "B14" at 124.46,72.644 h1
  text "B11" at 124.714,65.024 h1
  text "OUT V+" at 82.296,59.436 h1 r90
  text "GND" at 84.582,59.436 h1 r90
  text "C0" at 109.22,59.436 h1 r90
  text "C1" at 111.506,59.436 h1 r90
Bottom Layer:
  text "+" at 121.92,92.71 h1
  text "D2" at 80.01,91.694 h1 r270
  text "C12" at 115.57,91.44 h1 r270
  text "C11" at 118.11,91.44 h1 r270
  text "A14" at 122.174,90.424 h1
  text "RESET" at 82.55,88.392 h1 r270
  text "-" at 121.666,87.63 h1
  text "A13" at 121.666,85.09 h1 r318.01
  text "SWD" at 124.714,82.804 h1
  text "STM32" at 109.474,72.898 h1.52 r270
  text "A0" at 87.63,59.436 h1 r270
  text "A1" at 90.17,59.436 h1 r270
  text "A2" at 92.71,59.436 h1 r270
  text "A3" at 95.25,59.436 h1 r270
  text "A5" at 100.33,59.436 h1 r270

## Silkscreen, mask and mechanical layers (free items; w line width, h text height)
Mechanical 1:
  lines w0.2: 79.056,56.388 79.056,64.988 79.056,97.028 130.048,97.028 130.048,56.388 79.056,56.388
